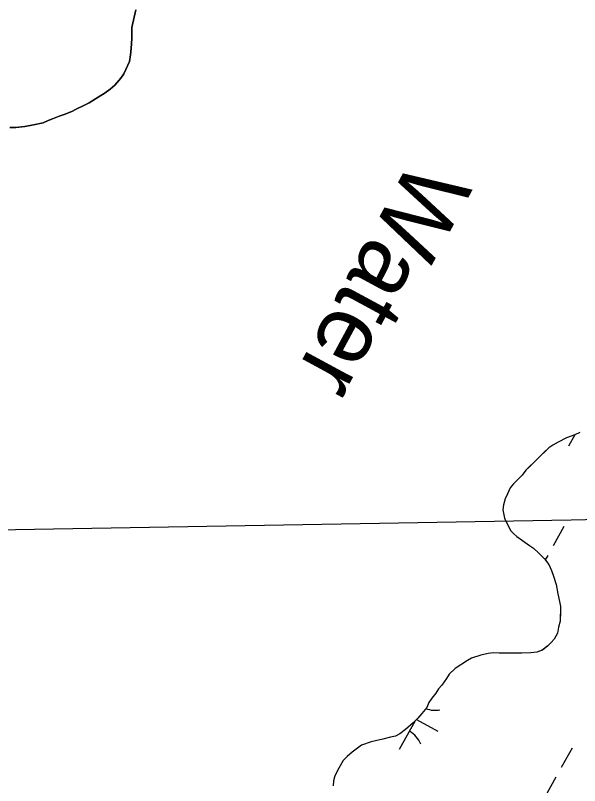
# Model space of a CAD drawing. Extents: x 3923531 to 3943530, y 207391 to 229799.
# Drawn here: x 3932547 to 3932955, y 217762 to 218319 of the extents above; entities that cross this region are included whole.
import ezdxf

# ---------------------------------------------------------------- set-up
doc = ezdxf.new("R2010")
doc.units = 0
for name, color, linetype in [('V-GRID-MAJR', 7, 'Continuous'), ('V-RIVR-IDEN', 7, 'Continuous'), ('V-TOPO-SHOR', 7, 'Continuous'), ('V-WETL-SWMP', 7, 'Continuous')]:
    doc.layers.add(name, color=color, linetype=linetype)

msp = doc.modelspace()

# ---------------------------------------------------------------- linework, layer by layer
at = {"layer": 'V-GRID-MAJR'}
msp.add_spline([(3929435.52, 217891.88), (3930329.23, 217907.73), (3935652.4, 218002.59), (3939803.52, 218077.1)], degree=3, dxfattribs=at)
at = {"layer": 'V-TOPO-SHOR'}
for points in [[(3932543.21, 218237.89), (3932547.61, 218237.85), (3932554.02, 218238.58), (3932560.43, 218239.71), (3932567.24, 218241.24), (3932570.86, 218242.81), (3932574.07, 218243.97), (3932578.89, 218245.92), (3932582.5, 218247.08), (3932588.12, 218249.43), (3932591.33, 218250.99), (3932597.77, 218254.12), (3932600.58, 218255.7), (3932607.02, 218259.63), (3932612.25, 218262.77), (3932615.88, 218265.53), (3932619.11, 218268.3), (3932623.56, 218273.45), (3932625.59, 218276.63), (3932627.22, 218279.81), (3932629.68, 218285.38), (3932630.53, 218290.18), (3932630.98, 218294.97), (3932631.46, 218302.16), (3932631.5, 218306.16), (3932631.54, 218310.16), (3932634.49, 218322.79)], [(3932955.62, 218017.29), (3932952, 218015.72), (3932945.98, 218013.39), (3932939.95, 218010.25), (3932935.93, 218008.29), (3932933.11, 218006.32), (3932929.47, 218002.76), (3932926.64, 217999.99), (3932923.82, 217997.22), (3932919.37, 217992.87), (3932916.54, 217990.1), (3932913.71, 217986.53), (3932910.07, 217982.57), (3932907.65, 217980.19), (3932905.22, 217977.42), (3932903.17, 217973.04), (3932901.54, 217969.46), (3932900.29, 217965.07), (3932899.85, 217961.48), (3932900.99, 217955.47), (3932903.34, 217950.65), (3932905.3, 217946.62), (3932907.67, 217944.2), (3932910.05, 217942.18), (3932914.02, 217939.34), (3932919.18, 217935.68), (3932921.96, 217933.66), (3932925.92, 217930.02), (3932929.88, 217925.98), (3932933.03, 217921.94), (3932934.99, 217917.52), (3932936.55, 217913.51), (3932938.48, 217907.49), (3932939.61, 217900.68), (3932940.75, 217895.07), (3932941.52, 217891.47), (3932941.48, 217887.87), (3932941.41, 217881.07), (3932940.17, 217876.68), (3932939.32, 217872.29), (3932936.87, 217867.92), (3932934.85, 217865.54), (3932932.43, 217863.17), (3932928.4, 217860.01), (3932924.38, 217858.45), (3932919.98, 217858.1), (3932913.58, 217857.76), (3932909.98, 217857.8), (3932905.98, 217857.84), (3932900.38, 217857.9), (3932897.18, 217857.93), (3932893.18, 217857.98), (3932889.18, 217857.62), (3932883.97, 217856.47), (3932877.15, 217854.14), (3932874.33, 217852.57), (3932865.47, 217846.67), (3932861.03, 217842.71), (3932859, 217839.54), (3932855.75, 217834.77), (3932853.33, 217831.99), (3932851.29, 217828.82), (3932848.46, 217825.25), (3932846.42, 217822.07), (3932844.79, 217818.49), (3932841.14, 217814.12), (3932838.31, 217810.96), (3932835.08, 217807.39), (3932829.43, 217802.65), (3932825.4, 217799.49), (3932822.18, 217797.93), (3932818.58, 217797.16), (3932812.96, 217795.62), (3932807.75, 217794.48), (3932804.54, 217793.71), (3932797.72, 217791.38), (3932790.87, 217786.25), (3932787.24, 217783.09)], [(3932787.24, 217783.09), (3932784.41, 217780.32), (3932781.15, 217774.76), (3932778.29, 217769.19), (3932777.46, 217765.6), (3932777.02, 217762)]]:
    msp.add_lwpolyline(points, dxfattribs=at)
at = {"layer": 'V-WETL-SWMP'}
for p, q in [((3932952, 218015.72), (3932945.98, 218013.38)), ((3932952.01, 218015.73), (3932947.36, 218007.4)), ((3932955.62, 218017.28), (3932952, 218015.72)), ((3932939.95, 218010.25), (3932935.93, 218008.29)), ((3932945.98, 218013.38), (3932939.95, 218010.25)), ((3932933.11, 218006.32), (3932916.55, 217990.1)), ((3932935.93, 218008.29), (3932933.11, 218006.32)), ((3932916.55, 217990.1), (3932913.71, 217986.53)), ((3932910.07, 217982.56), (3932907.64, 217980.19)), ((3932913.71, 217986.53), (3932910.07, 217982.56)), ((3932905.22, 217977.42), (3932903.17, 217973.04)), ((3932907.64, 217980.19), (3932905.22, 217977.42)), ((3932903.17, 217973.04), (3932901.54, 217969.46)), ((3932901.54, 217969.46), (3932900.29, 217965.07)), ((3932900.29, 217965.07), (3932899.85, 217961.48)), ((3932899.85, 217961.48), (3932900.99, 217955.47)), ((3932900.99, 217955.47), (3932905.3, 217946.62)), ((3932944, 217949.37), (3932936.2, 217935.4)), ((3932905.3, 217946.62), (3932907.67, 217944.2)), ((3932907.67, 217944.2), (3932910.05, 217942.18)), ((3932910.05, 217942.18), (3932914.02, 217939.34)), ((3932914.02, 217939.34), (3932919.18, 217935.68)), ((3932919.18, 217935.68), (3932921.96, 217933.66)), ((3932921.96, 217933.66), (3932925.92, 217930.02)), ((3932925.92, 217930.02), (3932929.88, 217925.98)), ((3932932.3, 217928.42), (3932930.49, 217925.19)), ((3932929.88, 217925.98), (3932933.03, 217921.94)), ((3932933.03, 217921.94), (3932934.99, 217917.52)), ((3932934.99, 217917.52), (3932936.55, 217913.51)), ((3932936.55, 217913.51), (3932938.48, 217907.49)), ((3932938.48, 217907.49), (3932939.61, 217900.68)), ((3932939.61, 217900.68), (3932940.75, 217895.07)), ((3932940.75, 217895.07), (3932941.52, 217891.46)), ((3932941.52, 217891.46), (3932941.41, 217881.07)), ((3932940.16, 217876.68), (3932939.32, 217872.29)), ((3932941.41, 217881.07), (3932940.16, 217876.68)), ((3932939.32, 217872.29), (3932936.87, 217867.92)), ((3932934.85, 217865.54), (3932932.43, 217863.17)), ((3932936.87, 217867.92), (3932934.85, 217865.54)), ((3932928.39, 217860.01), (3932924.38, 217858.45)), ((3932932.43, 217863.17), (3932928.39, 217860.01)), ((3932877.15, 217854.14), (3932874.33, 217852.57)), ((3932883.97, 217856.47), (3932877.15, 217854.14)), ((3932889.18, 217857.62), (3932883.97, 217856.47)), ((3932893.18, 217857.97), (3932889.18, 217857.62)), ((3932913.58, 217857.76), (3932893.18, 217857.97)), ((3932919.98, 217858.1), (3932913.58, 217857.76)), ((3932924.38, 217858.45), (3932919.98, 217858.1)), ((3932874.33, 217852.57), (3932865.47, 217846.66)), ((3932865.47, 217846.66), (3932861.03, 217842.71)), ((3932859, 217839.53), (3932855.75, 217834.77)), ((3932861.03, 217842.71), (3932859, 217839.53)), ((3932853.33, 217831.99), (3932851.29, 217828.82)), ((3932855.75, 217834.77), (3932853.33, 217831.99)), ((3932851.29, 217828.82), (3932848.46, 217825.25)), ((3932846.42, 217822.07), (3932844.79, 217818.49)), ((3932848.46, 217825.25), (3932846.42, 217822.07)), ((3932844.79, 217818.49), (3932841.14, 217814.13)), ((3932838.31, 217810.96), (3932835.08, 217807.39)), ((3932837.43, 217809.99), (3932852.87, 217801.36)), ((3932841.14, 217814.13), (3932838.31, 217810.96)), ((3932836.49, 217808.95), (3932824.96, 217788.31)), ((3932835.08, 217807.39), (3932829.43, 217802.65)), ((3932825.4, 217799.49), (3932822.18, 217797.93)), ((3932829.43, 217802.65), (3932825.4, 217799.49)), ((3932804.54, 217793.71), (3932797.72, 217791.38)), ((3932807.75, 217794.48), (3932804.54, 217793.71)), ((3932812.96, 217795.62), (3932807.75, 217794.48)), ((3932818.57, 217797.16), (3932812.96, 217795.62)), ((3932822.18, 217797.93), (3932818.57, 217797.16)), ((3932797.72, 217791.38), (3932790.87, 217786.25)), ((3932949.89, 217789.21), (3932942.08, 217775.24)), ((3932787.24, 217783.09), (3932784.41, 217780.32)), ((3932790.87, 217786.25), (3932787.24, 217783.09)), ((3932784.41, 217780.32), (3932781.15, 217774.76)), ((3932781.15, 217774.76), (3932778.3, 217769.19)), ((3932777.46, 217765.6), (3932777.02, 217762)), ((3932778.3, 217769.19), (3932777.46, 217765.6)), ((3932938.18, 217768.25), (3932930.38, 217754.29))]:
    msp.add_line(p, q, dxfattribs=at)
msp.add_lwpolyline([(3932634.49, 218322.79), (3932631.54, 218310.16), (3932631.5, 218306.16), (3932631.46, 218302.16), (3932630.98, 218294.97), (3932630.53, 218290.18), (3932629.68, 218285.39), (3932627.22, 218279.81), (3932625.59, 218276.63), (3932623.56, 218273.45), (3932619.11, 218268.3), (3932615.88, 218265.53), (3932612.25, 218262.77), (3932607.02, 218259.63), (3932600.58, 218255.7), (3932597.77, 218254.12), (3932591.34, 218250.99), (3932588.12, 218249.43), (3932582.5, 218247.08), (3932578.89, 218245.92), (3932574.07, 218243.97), (3932570.86, 218242.81), (3932567.24, 218241.24), (3932560.43, 218239.71), (3932554.02, 218238.58), (3932547.61, 218237.85), (3932543.21, 218237.89)], dxfattribs=at)
for centre, start, end in [((3932850.84, 217834.14), 247.9412, 281.5817), ((3932823.89, 217785.91), 20.0381, 61.5817)]:
    msp.add_arc(centre, 17.62, start, end, dxfattribs=at)

# ---------------------------------------------------------------- texts
at = {"layer": 'V-RIVR-IDEN'}
msp.add_text('Water', height=50, rotation=241.5894, dxfattribs=at).set_placement((3932834.13, 218216.85))

doc.saveas('drawing.dxf')
